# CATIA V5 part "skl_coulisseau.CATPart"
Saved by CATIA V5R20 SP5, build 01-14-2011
Part number: skl_coulisseau
Publications: "Point.1", "Axe_glissiere_coulisseau_bati", "Plan_glissiere_coulisseau_bati", "Axe_pivot_coulisseau_bielle_4", "Plan_ref"
Bounding box of the stored display mesh (mm): x -10 to 10, y 40 to 140, z 100 to 100
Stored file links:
  U:\2A\IAO\ThinkMotion\skl_coulisseau.CATPart
  U:\2A\IAO\ThinkMotion\skl.CATProduct
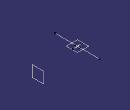
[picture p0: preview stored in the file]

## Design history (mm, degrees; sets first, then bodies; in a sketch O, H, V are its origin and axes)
Set1
  Point1: linked copy from another document
  Plane1 "Plan_ref": linked copy from another document
Set2
  Line1: type PtDir, RefPoint Point1, Direction zx-plane, Start -5, End 5
  Line2 "Axe_glissiere_coulisseau_bati": type PtDir, RefPoint Point1, Direction zx-plane, Start -50, End 50
  Plane2 "Plan_glissiere_coulisseau_bati": type OffsetPt, RefPlane xy-plane, RefPoint Point1
  Line3 "Axe_pivot_coulisseau_bielle_4": type Normal, RefPoint Point1, RefSkin Plane1, Start -10, End 10
Body1 (main body)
